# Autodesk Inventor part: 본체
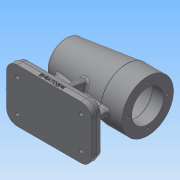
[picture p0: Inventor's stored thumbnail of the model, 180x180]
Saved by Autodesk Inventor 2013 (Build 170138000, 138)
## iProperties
Created: 2017-01
Part Number: 본체
Material: 일반
Document SubType Name: Modeling
Designer: Administrator
Density: 1 g/cm^3
Author: Administrator
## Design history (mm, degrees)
sketch "스케치2"
  geometry: L1 (0, 0)-(112, 0); L2 (112, 0)-(112, 34); L3 (112, 34)-(84.183, 34); L4 (83.818, 33.978)-(5.669, 24.382); A1 r 80 centre (80, 0) between (3.153, 22.238) and (0, 0); A2 r 3 centre (84.183, 31) between (84.183, 34) and (83.818, 33.978); A3 r 3 centre (6.035, 21.405) between (5.669, 24.382) and (3.153, 22.238); 2 further points
  constraints: 8 end point, 7 point on circle, 4 point on line, 4 tangent, 3 centre point, 2 perpendicular, 1 horizontal
  dimensions: "d2" = 112 distance of L1.start L1.end; "d3" = 28 distance of L2.end point (84, 34); "d4" = 7 deg angle of L3 L4; "d5" = 80 radius of A1; "d6" = 68 diameter of L3 L1; "d7" = 3 radius of A2; "d8" = 3 radius of A3
revolve "회전1" sketch "스케치2" stored, may be unused: angle "d9" = 90 deg
sketch "스케치3"
  geometry: L1 (0, 0)-(114.723, 0); L2 (6, 0)-(6, 7.5); L3 (9, 10.5)-(9, 10.5); L4 (9, 10.5)-(9, 15.7); L5 (9.3, 16)-(13, 16); L6 (13, 16)-(13, 17.2); L7 (13.3, 17.5)-(31, 17.5); L8 (31, 17.5)-(31, 20.7); L9 (31.3, 21)-(43, 21); L10 (43, 21)-(43, 21); L11 (46, 24)-(94, 24); L12 (97, 21)-(97, 21); L13 (97, 21)-(112, 21); L14 (112, -34)-(112, 34) reference; L15 (112, 21)-(112, 0); L16 (6, 0)-(112, 0); A1 r 3 centre (9, 7.5) between (9, 10.5) and (6, 7.5); A2 r 3 centre (46, 21) between (46, 24) and (43, 21); A3 r 3 centre (94, 21) between (97, 21) and (94, 24); A4 r 0.3 centre (9.3, 15.7) between (9.3, 16) and (9, 15.7); A5 r 0.3 centre (13.3, 17.2) between (13.3, 17.5) and (13, 17.2); A6 r 0.3 centre (31.3, 20.7) between (31.3, 21) and (31, 20.7); 4 further points
  constraints: 30 end point, 12 point on circle, 12 tangent, 10 parallel, 10 point on line, 6 centre point, 4 equal radius, 2 perpendicular, 1 collinear, 1 horizontal, 1 midpoint
  dimensions: "d10" = 15 distance from line of L14 L12.end; "d11" = 54 distance of L12.end L9.end; "d12" = 12 distance of point (31, 21) L9.end; "d13" = 18 distance of point (13, 17.5) L7.end; "d14" = 4 distance of point (9, 16) L5.end; "d15" = 3 distance of point (6, 10.5) L3.end; "d16" = 21 diameter of L3 L1; "d17" = 32 diameter of L5 L1; "d18" = 35 diameter of L7 L1; "d19" = 42 diameter of L9 L1; "d20" = 48 diameter of L11 L1; "d21" = 42 diameter of L13 L1; "d22" = 3 radius of A1; "d23" = 0.3 radius of A4
revolve "회전2" sketch "스케치3" stored, may be unused: angle "d24" = 90 deg
sketch "스케치4" dims "d26" = 52
  geometry: C1 r 21 at (0, 0) reference; C2 r 34 at (0, 0) reference; 3 further points
  constraints: 2 vertical alignment, 1 coincident, 2 other
hole "구멍1" sketch "스케치4" at (0, 26) diameter "d27" = 3.242; stored, may be unused: countersink angle "d31" = 90 deg, drill point angle "d33" = 118 deg; dims "d28" = 8, "d29" = 4, "d30" = 2, "d32" = 11
node "작업 평면1"
sketch "스케치5"
  geometry: 1 further point
sketch "스케치6"
  geometry: L1 (0, -35)-(-112, -35); L2 (-112, -35)-(-112, 35); L3 (-112, 35)-(0, 35); L4 (0, 35)-(0, -35); L5 (-112, 34)-(-112, -34) reference; L6 (-5.669, -24.382)-(-83.818, -33.978) reference; L7 (-5.669, 24.382)-(-83.818, 33.978) reference; 3 further points
  constraints: 8 end point, 2 midpoint, 2 parallel, 1 coincident, 1 horizontal, 1 perpendicular
  dimensions: "d38" = 112 distance of L2.end L3.end; "d39" = 70 distance of L1.end L2.end
extrude "돌출1" join sketch "스케치6" distance "d40" = 7; taper "d41" = 0 deg
fillet "모깎기1" dims "d42" = 14
sketch "스케치8"
  geometry: L1 (98, 35)-(14, 35) reference; L2 (0, 21)-(0, -21) reference; L3 (14, -35)-(98, -35) reference; L4 (112, -21)-(112, 21) reference; A1 r 14 centre (14, 21) between (14, 35) and (0, 21) reference; A2 r 14 centre (14, -21) between (0, -21) and (14, -35) reference; A3 r 14 centre (98, -21) between (98, -35) and (112, -21) reference; A4 r 14 centre (98, 21) between (112, 21) and (98, 35) reference; 1 further point
extrude "돌출2" join sketch "스케치8" distance "d43" = 7; taper "d44" = -15 deg
sketch "스케치11"
  geometry: L1 (18, 4)-(94, 4); L2 (94, 4)-(94, -4); L3 (94, -4)-(18, -4); L4 (18, -4)-(18, 4); L5 (18, 0)-(78.227, 0); L6 (98, -35)-(14, -35) reference; L7 (112, 21)-(112, -21) reference; L8 (0, -21)-(0, 21) reference; 1 further point
  constraints: 10 end point, 2 parallel, 1 horizontal, 1 midpoint, 1 perpendicular
  dimensions: "d49" = 8 distance between parallel lines of L3 L1; "d50" = 35 distance between parallel lines of L6 L5; "d52" = 18 distance between parallel lines of L4 L8; "d53" = 18 distance between parallel lines of L7 L2
extrude "돌출3" join sketch "스케치11" stored distance "d54" = 7; taper "d55" = 0 deg
node "작업 평면2"
sketch "스케치12"
  geometry: L1 (-67, 35)-(-60, 33.124) reference; L2 (-60, 33.124)-(-60, 4) reference; L3 (-60, 4)-(-30.299, 4) reference; L4 (-30.299, -4)-(-60, -4) reference; L5 (-60, -4)-(-60, -33.124) reference; L6 (-60, -33.124)-(-67, -35) reference; L7 (-67, -35)-(-74, -35) reference; L8 (-74, -35)-(-74, 35) reference; L9 (-74, 35)-(-67, 35) reference; L10 (-25.458, 16.909)-(-60, 23); L11 (-25.458, -16.909)-(-60, -23); C1 r 24 at (0, 0) reference; A1 r 30.562 centre (0, 0) between (-30.299, -4) and (-30.299, 4) reference; 1 further point
  constraints: 4 end point, 2 point on circle, 2 point on line
  dimensions: "d57" = 100 deg angle of L2 L10; "d58" = 12 distance from line of L10.end L9; "d59" = 100 deg angle of L5 L11; "d60" = 12 distance from line of L7 L11.end
  node "절단 모서리 투영1"
feature "리브1" dims "d61" = 1, "d62" = 8, "d63" = 0, "d64" = 0, "d65" = 1, "d66" = 1
feature "리브2" dims "d67" = 1, "d68" = 8, "d69" = 0, "d70" = 0, "d71" = 1, "d72" = 1
fillet "모깎기2" dims "d73" = 3
fillet "모깎기3" dims "d74" = 3
fillet "모깎기4" dims "d75" = 3
fillet "모깎기5" dims "d76" = 1
sketch "스케치15" dims "d77" = 10, "d78" = 10, "d84" = 10, "d88" = 10
  geometry: L1 (0, -21)-(0, 21) reference; L2 (112, 21)-(112, -21) reference; L3 (98, -35)-(14, -35) reference; L4 (14, 35)-(98, 35) reference; L5 (16.887, -16)-(19.774, -21); L6 (19.774, -21)-(16.887, -26); L7 (16.887, -26)-(11.113, -26); L8 (11.113, -26)-(8.226, -21); L9 (8.226, -21)-(11.113, -16); L10 (11.113, -16)-(16.887, -16); L11 (100.887, -16)-(103.774, -21); L12 (103.774, -21)-(100.887, -26); L13 (100.887, -26)-(95.113, -26); L14 (95.113, -26)-(92.226, -21); L15 (92.226, -21)-(95.113, -16); L16 (95.113, -16)-(100.887, -16); L17 (100.887, 26)-(103.774, 21); L18 (103.774, 21)-(100.887, 16); L19 (100.887, 16)-(95.113, 16); L20 (95.113, 16)-(92.226, 21); L21 (92.226, 21)-(95.113, 26); L22 (95.113, 26)-(100.887, 26); L23 (16.887, 26)-(19.774, 21); L24 (19.774, 21)-(16.887, 16); L25 (16.887, 16)-(11.113, 16); L26 (11.113, 16)-(8.226, 21); L27 (8.226, 21)-(11.113, 26); L28 (11.113, 26)-(16.887, 26); C1 r 2.5 at (14, -21); C2 r 2.5 at (98, -21); C3 r 2.5 at (98, 21); C4 r 2.5 at (14, 21); 13 further points
  constraints: 48 end point, 8 coincident, 4 centre point, 4 midpoint, 4 vertical alignment, 60 other
  dimensions: "d79" = 84 distance of point (98, -21) point (14, -21); "d82" = 14 distance from line of point (14, -21) L1; "d83" = 14 distance from line of L2 point (98, -21); "d85" = 42 distance of point (14, -21) point (14, 21); "d86" = 14 distance from line of L3 point (14, -21); "d87" = 14 distance from line of point (14, 21) L4; "d89" = 42 distance of point (98, -21) point (98, 21); "d90" = 14 distance from line of L4 point (98, 21); "d93" = 5 diameter of C1; "d94" = 5 diameter of C2; "d95" = 5 diameter of C3; "d96" = 5 diameter of C4
extrude "돌출4" cut sketch "스케치15" distance "d91" = 4; taper "d92" = 0 deg
extrude "돌출5" cut sketch "스케치15" stored distance "d97" = 4; taper "d98" = 0 deg
sketch "스케치17"
  geometry: L1 (84, 0)-(0, 0) reference; L2 (98, 0)-(98, 7) reference; 2 further points
  constraints: 1 other
  dimensions: "d99" = 56 distance from line of L2 point (42, 4); "d100" = 4 distance from line of L1 point (42, 4)
feature "엠보싱1" sketch "스케치17" dims "d2" = 112, "d3" = 28, "d4" = 7 deg, "d5" = 80, "d6" = 68, "d7" = 3, "d8" = 3, "d10" = 15, "d11" = 54, "d12" = 12, "d13" = 18, "d14" = 4, "d15" = 3, "d16" = 21, "d17" = 32, "d18" = 35, "d19" = 42, "d20" = 48, "d21" = 42, "d22" = 3, "d23" = 0.3, "d101" = 0.5, "d102" = 0
node "솔리드1"
pattern_circular "원형 패턴1" dims angle "d35" = 360 deg
node "투영된 루프1"
other parameters: "d37" = -74, "d56" = 56
